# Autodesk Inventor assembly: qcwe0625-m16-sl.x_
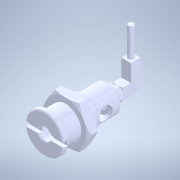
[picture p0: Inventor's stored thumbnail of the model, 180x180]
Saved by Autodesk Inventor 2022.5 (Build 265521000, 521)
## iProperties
Created: 2023-04
Part Number: qcwe0625-m16-sl.x_
Document SubType Name: Assembly
Designer: ImaoCorp
Sending System: SOLIDWORKS 2021-2021301
MC: AMD64
MC_MODEL: Intel64 Family 6 Model 60 Stepping 3, GenuineIntel
OS: Windows_NT
FRU: Parasolid Version 32.1, build 255,  1- 1-2021
FORMAT: text
GUISE: transmit
KEY: qcwe0625-m16-sl
FILE: qcwe0625-m16-sl.x_t
DATE: Fri Apr  7 10:56:08 2023
Author: ImaoCorp
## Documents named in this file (4)
- X:\14_SW2022-Inv2022\00_全2023-1023新製品(TCC)まで\q\qcwe0625-m16-sl\QCWE0625-M16-SL.iam
- X:\14_SW2022-Inv2022\00_全2023-1023新製品(TCC)まで\q\qcwe0625-m16-sl\qcwe0625-m16-sl_01.ipt
- X:\14_SW2022-Inv2022\00_全2023-1023新製品(TCC)まで\q\qcwe0625-m16-sl\qcwe0625-m16-sl_02.ipt
- X:\14_SW2022-Inv2022\00_全2023-1023新製品(TCC)まで\q\qcwe0625-m16-sl\qcwe0625-m16-sl_03.ipt
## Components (3 placed, 3 different names)
1. qcwe0625-m16-sl_01
2. qcwe0625-m16-sl_02
3. qcwe0625-m16-sl_03
